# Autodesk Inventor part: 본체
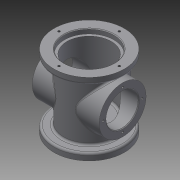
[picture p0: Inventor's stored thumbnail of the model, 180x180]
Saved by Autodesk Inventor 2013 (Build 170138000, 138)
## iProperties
Created: 2018-02
Part Number: 본체
Material: 일반
Document SubType Name: Modeling
Designer: Administrator
Density: 1 g/cm^3
Author: Administrator
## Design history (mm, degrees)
sketch "스케치1"
  geometry: C1 r 38 at (0, 0); 1 further point
  constraints: 1 centre point, 1 coincident
  dimensions: "d0" = 76 diameter of C1
extrude "돌출1" new body sketch "스케치1" stored distance "d2" = 88; taper "d3" = 0 deg
sketch "스케치2"
  geometry: C1 r 38 at (0, 0) reference; C2 r 52.5 at (0, 0)
  constraints: 1 centre point, 1 coincident
  dimensions: "d5" = 105 diameter of C2
extrude "돌출2" join sketch "스케치2" distance "d7" = 10; taper "d8" = 0 deg
hole "구멍1" diameter "d11" = 66; stored, may be unused: countersink angle "d15" = 90 deg, drill point angle "d17" = 0 deg; dims "d9" = 10, "d10" = 10, "d12" = 6, "d13" = 74, "d14" = 7, "d16" = 86
hole "구멍2" diameter "d20" = 10; stored, may be unused: countersink angle "d24" = 90 deg, drill point angle "d26" = 0 deg; dims "d18" = 10, "d19" = 10, "d21" = 6, "d22" = 68, "d23" = 16, "d25" = 22
node "작업 평면1"
sketch "스케치3"
  geometry: C1 r 35 at (0, 0); 1 further point
  constraints: 1 centre point, 1 coincident
  dimensions: "d29" = 70 diameter of C1
extrude "돌출3" join sketch "스케치3" stored distance "d31" = 10; taper "d32" = 0 deg
hole "구멍3" diameter "d35" = 48; stored, may be unused: countersink angle "d39" = 90 deg, drill point angle "d41" = 0 deg; dims "d33" = 10, "d34" = 10, "d36" = 6, "d37" = 68, "d38" = 16, "d40" = 22
sketch "스케치4"
  geometry: C1 r 24 at (0, 0) reference; 1 further point
  constraints: 1 vertical alignment
  dimensions: "d42" = 29 distance of C1.centre point (0, 29)
hole "구멍4" sketch "스케치4" at (0, 29) diameter "d43" = 3.242; stored, may be unused: countersink angle "d47" = 90 deg, drill point angle "d49" = 118 deg; dims "d44" = 4, "d45" = 68, "d46" = 16, "d48" = 6
sketch "스케치5"
  geometry: C1 r 37 at (0, 0) reference; 1 further point
  constraints: 1 vertical alignment
  dimensions: "d53" = 45 distance of C1.centre point (0, 45)
hole "구멍5" sketch "스케치5" at (0, 45) diameter "d54" = 3.242; stored, may be unused: countersink angle "d58" = 90 deg, drill point angle "d60" = 118 deg; dims "d55" = 4, "d56" = 68, "d57" = 16, "d59" = 6
node "작업 평면2"
sketch "스케치6"
  geometry: L1 (-7, 13)-(-7, -13); L2 (7, 13)-(7, -13); A1 r 7 centre (0, 13) between (7, 13) and (-7, 13); A2 r 7 centre (0, -13) between (-7, -13) and (7, -13); 2 further points
  constraints: 4 end point, 4 point on circle, 4 tangent, 2 centre point, 2 vertical alignment, 1 equal radius, 1 horizontal alignment, 1 midpoint
  dimensions: "d65" = 14 diameter of A1; "d69" = 40 dimension on A2 A1
extrude "돌출4" join sketch "스케치6" stored distance "d70" = 10; taper "d71" = 15 deg
hole "구멍6" diameter "d74" = 4.134; stored, may be unused: countersink angle "d78" = 90 deg, drill point angle "d80" = 118 deg; dims "d72" = 10, "d73" = 10, "d75" = 6, "d76" = 68, "d77" = 16, "d79" = 8
hole "구멍7" diameter "d83" = 4.134; stored, may be unused: countersink angle "d87" = 90 deg, drill point angle "d89" = 118 deg; dims "d81" = 10, "d82" = 10, "d84" = 6, "d85" = 68, "d86" = 16, "d88" = 8
fillet "모깎기1" dims "d90" = 3
fillet "모깎기2" dims "d91" = 3
fillet "모깎기3" dims "d92" = 3
fillet "모깎기4" dims "d93" = 3
fillet "모깎기5" dims "d94" = 3
chamfer "모따기1" distance "d95" = 1; stored, may be unused: second distance "d96" = 2, angle "d97" = 45 deg
sketch "스케치7"
  geometry: C1 r 49.5 at (0, 0) reference; C2 r 43 at (0, 0)
  constraints: 1 centre point, 1 coincident, 1 other
  dimensions: "d101" = 86 diameter of C2
feature "엠보싱1" sketch "스케치7" dims "d103" = 0.5, "d104" = 0
chamfer "모따기2" distance "d105" = 1; stored, may be unused: second distance "d106" = 2, angle "d107" = 45 deg
node "솔리드1"
mirror "대칭1"
pattern_circular "원형 패턴1" dims angle "d51" = 360 deg
mirror "대칭2"
pattern_circular "원형 패턴2" dims angle "d62" = 360 deg
other parameters: "d64" = 55
